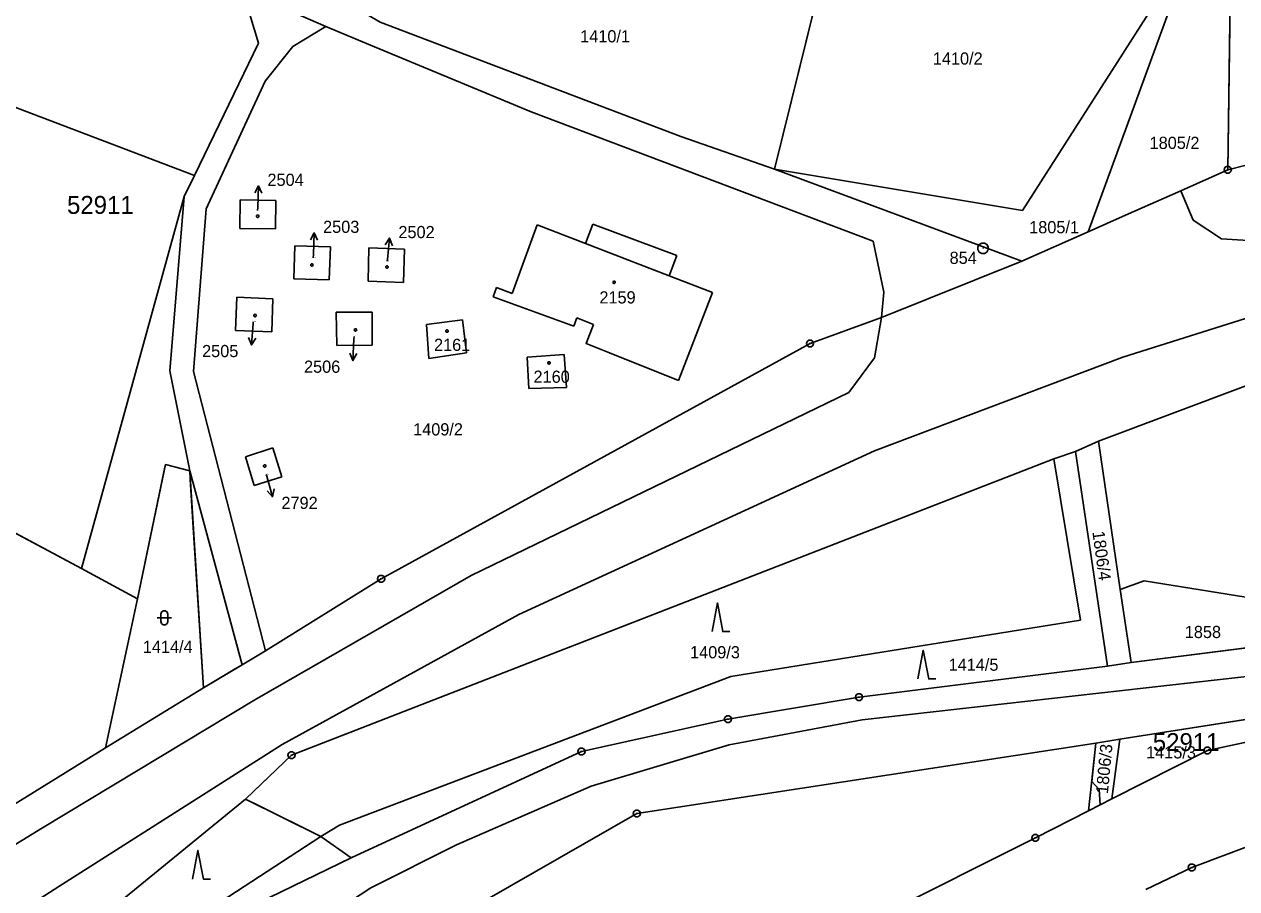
# Model space of a CAD drawing. Extents: x -779618 to -776429, y -1144546 to -1143350.
# Drawn here: x -778303.8 to -778134.6, y -1143722.3 to -1143601.8 of the extents above; entities that cross this region are included whole.
import ezdxf

# ---------------------------------------------------------------- set-up
doc = ezdxf.new("R2010")
doc.units = 0
for name, color, linetype in [('1', 7, 'Continuous'), ('11', 7, 'Continuous'), ('12', 7, 'Continuous'), ('2', 7, 'Continuous'), ('3', 7, 'Continuous'), ('4', 7, 'Continuous'), ('5', 7, 'Continuous'), ('6', 7, 'Continuous'), ('7', 7, 'Continuous'), ('8', 7, 'Continuous')]:
    doc.layers.add(name, color=color, linetype=linetype)

msp = doc.modelspace()

# ---------------------------------------------------------------- linework, layer by layer
at = {"layer": '1'}
for p, q in [((-778199.09, -1143621.98), (-778188.17, -1143577.7)), ((-778164.47, -1143627.74), (-778140.52, -1143590.24)), ((-778155.33, -1143630.71), (-778140.52, -1143590.24)), ((-778135.85, -1143622.07), (-778135.46, -1143593.27)), ((-778271.09, -1143604.41), (-778273.31, -1143597.02)), ((-778273.31, -1143597.02), (-778261.68, -1143602.09)), ((-778261.68, -1143602.09), (-778255.47, -1143604.68)), ((-778254.1, -1143601.46), (-778212.15, -1143617.44)), ((-778280.01, -1143622.84), (-778271.09, -1143604.41)), ((-778255.47, -1143604.68), (-778233.02, -1143613.98)), ((-778305.7, -1143613.08), (-778280.01, -1143622.84)), ((-778233.02, -1143613.98), (-778185.33, -1143632)), ((-778135.85, -1143622.07), (-778102.74, -1143613.61)), ((-778212.15, -1143617.44), (-778199.09, -1143621.98)), ((-778399.27, -1143622.42), (-778295.76, -1143677.67)), ((-778281.44, -1143625.81), (-778280.01, -1143622.84)), ((-778199.09, -1143621.98), (-778164.47, -1143627.74)), ((-778164.6, -1143634.82), (-778199.09, -1143621.98)), ((-778135.85, -1143622.07), (-778142.39, -1143624.98)), ((-778295.76, -1143677.67), (-778281.44, -1143625.81)), ((-778273.67, -1143630.26), (-778273.62, -1143626.25)), ((-778273.62, -1143626.25), (-778268.64, -1143626.37)), ((-778268.64, -1143626.37), (-778268.71, -1143630.32)), ((-778150.11, -1143628.4), (-778142.39, -1143624.98)), ((-778235.69, -1143639.3), (-778232.18, -1143629.74)), ((-778232.18, -1143629.74), (-778225.48, -1143632.35)), ((-778225.48, -1143632.35), (-778224.44, -1143629.63)), ((-778224.44, -1143629.63), (-778212.7, -1143634)), ((-778150.11, -1143628.4), (-778155.33, -1143630.71)), ((-778268.71, -1143630.32), (-778273.67, -1143630.26)), ((-778155.33, -1143630.71), (-778164.6, -1143634.82)), ((-778266.15, -1143637.28), (-778266.02, -1143632.68)), ((-778266.02, -1143632.68), (-778261.04, -1143632.82)), ((-778261.04, -1143632.82), (-778261.23, -1143637.42)), ((-778255.76, -1143637.61), (-778255.69, -1143632.97)), ((-778255.69, -1143632.97), (-778250.69, -1143633.13)), ((-778250.69, -1143633.13), (-778250.86, -1143637.79)), ((-778185.33, -1143632), (-778183.84, -1143639.14)), ((-778212.7, -1143634), (-778213.8, -1143636.84)), ((-778164.6, -1143634.82), (-778184.18, -1143642.68)), ((-778261.23, -1143637.42), (-778266.15, -1143637.28)), ((-778250.86, -1143637.79), (-778255.76, -1143637.61)), ((-778213.8, -1143636.84), (-778207.75, -1143639.17)), ((-778274.29, -1143644.46), (-778274.12, -1143639.83)), ((-778274.12, -1143639.83), (-778269.1, -1143640.05)), ((-778238.35, -1143639.77), (-778237.86, -1143638.48)), ((-778227.1, -1143643.89), (-778238.35, -1143639.77)), ((-778237.86, -1143638.48), (-778235.69, -1143639.3)), ((-778207.75, -1143639.17), (-778211.37, -1143648.55)), ((-778184.18, -1143642.68), (-778183.84, -1143639.14)), ((-778269.1, -1143640.05), (-778269.23, -1143644.64)), ((-778260.24, -1143641.93), (-778255.24, -1143641.93)), ((-778260.16, -1143646.56), (-778260.24, -1143641.93)), ((-778255.24, -1143641.93), (-778255.2, -1143646.51)), ((-778247.64, -1143643.63), (-778242.6, -1143643.01)), ((-778242.6, -1143643.01), (-778242.04, -1143647.59)), ((-778226.66, -1143642.73), (-778227.1, -1143643.89)), ((-778224.33, -1143643.62), (-778226.66, -1143642.73)), ((-778194.13, -1143646.31), (-778184.18, -1143642.68)), ((-778269.23, -1143644.64), (-778274.29, -1143644.46)), ((-778247.31, -1143648.36), (-778247.64, -1143643.63)), ((-778255.2, -1143646.51), (-778260.16, -1143646.56)), ((-778253.97, -1143679.1), (-778194.13, -1143646.31)), ((-778242.04, -1143647.59), (-778247.31, -1143648.36)), ((-778228.42, -1143647.83), (-778233.6, -1143648.2)), ((-778233.6, -1143648.2), (-778233.38, -1143652.56)), ((-778228.09, -1143652.44), (-778228.42, -1143647.83)), ((-778212.48, -1143651.43), (-778222.12, -1143647.61)), ((-778211.37, -1143648.55), (-778212.48, -1143651.43)), ((-778233.38, -1143652.56), (-778228.09, -1143652.44)), ((-778153.87, -1143659.9), (-778133.34, -1143652.18)), ((-778157.08, -1143661.33), (-778153.87, -1143659.9)), ((-778153.87, -1143659.9), (-778150.86, -1143680.58)), ((-778272.91, -1143662.07), (-778269.08, -1143660.84)), ((-778269.08, -1143660.84), (-778267.84, -1143664.89)), ((-778160.14, -1143662.37), (-778157.08, -1143661.33)), ((-778157.08, -1143661.33), (-778152.63, -1143691.27)), ((-778287.96, -1143681.89), (-778284.07, -1143663.17)), ((-778284.07, -1143663.17), (-778280.67, -1143664.05)), ((-778271.7, -1143666.07), (-778272.91, -1143662.07)), ((-778160.14, -1143662.37), (-778266.47, -1143703.7)), ((-778160.14, -1143662.37), (-778156.42, -1143684.85)), ((-778278.76, -1143694.3), (-778280.67, -1143664.05)), ((-778267.84, -1143664.89), (-778271.7, -1143666.07)), ((-778295.76, -1143677.67), (-778287.96, -1143681.89)), ((-778270.08, -1143689.13), (-778253.97, -1143679.1)), ((-778147.52, -1143679.38), (-778150.86, -1143680.58)), ((-778149.31, -1143690.75), (-778150.86, -1143680.58)), ((-778149.31, -1143690.75), (-778058.53, -1143679.28)), ((-778118.06, -1143684.08), (-778147.52, -1143679.38)), ((-778292.44, -1143702.68), (-778287.96, -1143681.89)), ((-778156.42, -1143684.85), (-778205.17, -1143692.74)), ((-778273.37, -1143691.09), (-778270.08, -1143689.13)), ((-778152.63, -1143691.27), (-778149.31, -1143690.75)), ((-778278.76, -1143694.3), (-778273.37, -1143691.09)), ((-778187.29, -1143695.6), (-778152.63, -1143691.27)), ((-778205.17, -1143692.74), (-778259.76, -1143713.44)), ((-778292.44, -1143702.68), (-778278.76, -1143694.3)), ((-778205.58, -1143698.68), (-778187.29, -1143695.6)), ((-778150.93, -1143701.48), (-778109.8, -1143695.04)), ((-778109.45, -1143696.76), (-778138.69, -1143703.04)), ((-778226.02, -1143703.2), (-778205.58, -1143698.68)), ((-778154.26, -1143702.04), (-778218.29, -1143711.84)), ((-778155.29, -1143711.47), (-778154.26, -1143702.04)), ((-778150.93, -1143701.48), (-778154.26, -1143702.04)), ((-778150.93, -1143701.48), (-778152.04, -1143709.77)), ((-778314.85, -1143716.56), (-778292.44, -1143702.68)), ((-778272.9, -1143709.81), (-778266.47, -1143703.7)), ((-778258.15, -1143717.99), (-778226.02, -1143703.2)), ((-778138.69, -1143703.04), (-778152.04, -1143709.77)), ((-778113.43, -1143708.98), (-778140.87, -1143719.35)), ((-778298.38, -1143730.62), (-778272.9, -1143709.81)), ((-778272.9, -1143709.81), (-778262.39, -1143715.02)), ((-778152.04, -1143709.77), (-778155.29, -1143711.47)), ((-778218.29, -1143711.84), (-778252.34, -1143731.3)), ((-778162.69, -1143715.23), (-778155.29, -1143711.47)), ((-778259.76, -1143713.44), (-778262.39, -1143715.02)), ((-778285.72, -1143730.23), (-778262.39, -1143715.02)), ((-778258.15, -1143717.99), (-778262.39, -1143715.02)), ((-778187.65, -1143727.69), (-778162.69, -1143715.23)), ((-778272.82, -1143725.14), (-778258.15, -1143717.99)), ((-778140.87, -1143719.35), (-778147.27, -1143722.43))]:
    msp.add_line(p, q, dxfattribs=at)
msp.add_lwpolyline([(-778224.33, -1143643.62), (-778225.38, -1143646.31), (-778222.12, -1143647.61)], dxfattribs=at)
at = {"layer": '11'}
for points in [[(-778309.93, -1143572.65), (-778265.53, -1143597.61), (-778264.74, -1143595.22), (-778254.1, -1143601.46), (-778212.15, -1143617.44), (-778199.09, -1143621.98), (-778194.74, -1143604.33), (-778188.17, -1143577.7), (-778140.52, -1143590.24), (-778144.08, -1143595.81), (-778135.53, -1143598.75), (-778135.85, -1143622.07)], [(-778391.62, -1143606.39), (-778399.27, -1143622.42), (-778398.95, -1143622.59), (-778295.76, -1143677.67), (-778287.96, -1143681.89), (-778284.15, -1143663.54), (-778284.07, -1143663.17), (-778280.67, -1143664.05), (-778280.59, -1143665.26), (-778280.22, -1143671.2), (-778278.76, -1143694.3)], [(-777931.96, -1143618.26), (-778063.42, -1143629.9), (-778133.34, -1143652.18), (-778153.87, -1143659.9), (-778157.08, -1143661.33), (-778160.14, -1143662.37), (-778266.47, -1143703.7), (-778271.68, -1143708.65), (-778272.9, -1143709.81), (-778271.17, -1143710.67), (-778262.39, -1143715.02), (-778258.15, -1143717.99), (-778226.02, -1143703.2), (-778205.58, -1143698.68), (-778187.29, -1143695.6), (-778152.63, -1143691.27), (-778149.31, -1143690.75), (-778058.53, -1143679.28), (-778043.88, -1143677.97), (-777959.48, -1143668.5)], [(-778278.76, -1143694.3), (-778274.32, -1143691.66), (-778273.37, -1143691.09), (-778270.08, -1143689.13), (-778253.97, -1143679.1), (-778194.13, -1143646.31), (-778184.18, -1143642.68), (-778164.6, -1143634.82), (-778155.33, -1143630.71), (-778150.11, -1143628.4), (-778142.39, -1143624.98), (-778135.85, -1143622.07)]]:
    msp.add_lwpolyline(points, dxfattribs=at)
msp.add_lwpolyline([(-778138.69, -1143703.04), (-778109.45, -1143696.76), (-778109.8, -1143695.04), (-778150.93, -1143701.48), (-778154.26, -1143702.04), (-778154.84, -1143707.34), (-778153.79, -1143708.48), (-778153.66, -1143710.62), (-778152.04, -1143709.77)], close=True, dxfattribs=at)
at = {"layer": '12'}
for p, q in [((-778273.67, -1143630.26), (-778273.62, -1143626.25)), ((-778273.62, -1143626.25), (-778268.64, -1143626.37)), ((-778268.64, -1143626.37), (-778268.71, -1143630.32)), ((-778235.69, -1143639.3), (-778232.18, -1143629.74)), ((-778232.18, -1143629.74), (-778225.48, -1143632.35)), ((-778268.71, -1143630.32), (-778273.67, -1143630.26)), ((-778266.15, -1143637.28), (-778266.02, -1143632.68)), ((-778266.02, -1143632.68), (-778261.04, -1143632.82)), ((-778261.04, -1143632.82), (-778261.23, -1143637.42)), ((-778255.76, -1143637.61), (-778255.69, -1143632.97)), ((-778255.69, -1143632.97), (-778250.69, -1143633.13)), ((-778250.69, -1143633.13), (-778250.86, -1143637.79)), ((-778225.48, -1143632.35), (-778213.8, -1143636.84)), ((-778261.23, -1143637.42), (-778266.15, -1143637.28)), ((-778250.86, -1143637.79), (-778255.76, -1143637.61)), ((-778213.8, -1143636.84), (-778207.75, -1143639.17)), ((-778274.29, -1143644.46), (-778274.12, -1143639.83)), ((-778274.12, -1143639.83), (-778269.1, -1143640.05)), ((-778238.35, -1143639.77), (-778237.86, -1143638.48)), ((-778227.1, -1143643.89), (-778238.35, -1143639.77)), ((-778237.86, -1143638.48), (-778235.69, -1143639.3)), ((-778207.75, -1143639.17), (-778211.37, -1143648.55)), ((-778269.1, -1143640.05), (-778269.23, -1143644.64)), ((-778260.24, -1143641.93), (-778255.24, -1143641.93)), ((-778260.16, -1143646.56), (-778260.24, -1143641.93)), ((-778255.24, -1143641.93), (-778255.2, -1143646.51)), ((-778247.64, -1143643.63), (-778242.6, -1143643.01)), ((-778242.6, -1143643.01), (-778242.04, -1143647.59)), ((-778226.66, -1143642.73), (-778227.1, -1143643.89)), ((-778224.33, -1143643.62), (-778226.66, -1143642.73)), ((-778269.23, -1143644.64), (-778274.29, -1143644.46)), ((-778247.31, -1143648.36), (-778247.64, -1143643.63)), ((-778255.2, -1143646.51), (-778260.16, -1143646.56)), ((-778242.04, -1143647.59), (-778247.31, -1143648.36)), ((-778228.42, -1143647.83), (-778233.6, -1143648.2)), ((-778233.6, -1143648.2), (-778233.38, -1143652.56)), ((-778228.09, -1143652.44), (-778228.42, -1143647.83)), ((-778212.48, -1143651.43), (-778222.12, -1143647.61)), ((-778211.37, -1143648.55), (-778212.48, -1143651.43)), ((-778233.38, -1143652.56), (-778228.09, -1143652.44)), ((-778272.91, -1143662.07), (-778269.08, -1143660.84)), ((-778269.08, -1143660.84), (-778267.84, -1143664.89)), ((-778271.7, -1143666.07), (-778272.91, -1143662.07)), ((-778267.84, -1143664.89), (-778271.7, -1143666.07))]:
    msp.add_line(p, q, dxfattribs=at)
msp.add_lwpolyline([(-778224.33, -1143643.62), (-778225.38, -1143646.31), (-778222.12, -1143647.61)], dxfattribs=at)
at = {"layer": '3'}
msp.add_lwpolyline([(-778284.72, -1143684.03), (-778284.62, -1143683.74), (-778284.37, -1143683.56), (-778284.06, -1143683.56), (-778283.81, -1143683.74), (-778283.71, -1143684.03), (-778283.71, -1143685.03), (-778283.81, -1143685.32), (-778284.06, -1143685.5), (-778284.37, -1143685.5), (-778284.62, -1143685.32), (-778284.72, -1143685.03)], close=True, dxfattribs=at)
for points in [[(-778207.8, -1143686.45), (-778207.05, -1143682.45), (-778206.3, -1143686.45), (-778205.3, -1143686.45)], [(-778285.22, -1143684.53), (-778283.95, -1143684.53), (-778283.22, -1143684.53)], [(-778179.08, -1143693.06), (-778178.33, -1143689.06), (-778177.58, -1143693.06), (-778176.58, -1143693.06)], [(-778280.27, -1143720.98), (-778279.52, -1143716.98), (-778278.77, -1143720.98), (-778277.77, -1143720.98)]]:
    msp.add_lwpolyline(points, dxfattribs=at)
at = {"layer": '4'}
for p, q in [((-778261.68, -1143602.09), (-778266.28, -1143604.87)), ((-778266.28, -1143604.87), (-778270.13, -1143609.7)), ((-778278.4, -1143627.53), (-778270.13, -1143609.7)), ((-778283.47, -1143650.09), (-778281.44, -1143625.81)), ((-778140.68, -1143629.11), (-778142.39, -1143624.98)), ((-778280.17, -1143650.2), (-778278.4, -1143627.53)), ((-778140.68, -1143629.11), (-778136.75, -1143631.7)), ((-778225.48, -1143632.35), (-778213.8, -1143636.84)), ((-778136.75, -1143631.7), (-778130.6, -1143632.07)), ((-778117.12, -1143637.64), (-778150.48, -1143648.2)), ((-778185.12, -1143648.27), (-778184.18, -1143642.68)), ((-778185.12, -1143648.27), (-778188.71, -1143653.12)), ((-778185.13, -1143661.25), (-778150.48, -1143648.2)), ((-778283.47, -1143650.09), (-778280.67, -1143664.05)), ((-778270.08, -1143689.13), (-778280.17, -1143650.2)), ((-778188.71, -1143653.12), (-778241.42, -1143678.62)), ((-778185.13, -1143661.25), (-778234.77, -1143684.06)), ((-778273.37, -1143691.09), (-778280.67, -1143664.05)), ((-778271.61, -1143695.99), (-778241.42, -1143678.62)), ((-778267.79, -1143702.21), (-778234.77, -1143684.06)), ((-778301.23, -1143713.82), (-778271.61, -1143695.99)), ((-778298.93, -1143721.99), (-778267.79, -1143702.21)), ((-778301.23, -1143713.82), (-778336.67, -1143735.43)), ((-778331.87, -1143743.04), (-778298.93, -1143721.99))]:
    msp.add_line(p, q, dxfattribs=at)
at = {"layer": '5'}
for points in [[(-778271.2, -1143628.37), (-778271.1, -1143628.39), (-778271.05, -1143628.48), (-778271.03, -1143628.54), (-778271.05, -1143628.63), (-778271.13, -1143628.7), (-778271.2, -1143628.71), (-778271.29, -1143628.68), (-778271.35, -1143628.62), (-778271.37, -1143628.54), (-778271.35, -1143628.45), (-778271.27, -1143628.38)], [(-778263.63, -1143635.17), (-778263.53, -1143635.19), (-778263.48, -1143635.28), (-778263.46, -1143635.34), (-778263.48, -1143635.43), (-778263.56, -1143635.5), (-778263.63, -1143635.51), (-778263.72, -1143635.48), (-778263.78, -1143635.42), (-778263.8, -1143635.34), (-778263.78, -1143635.25), (-778263.7, -1143635.18)], [(-778253.16, -1143635.45), (-778253.06, -1143635.47), (-778253.01, -1143635.56), (-778252.99, -1143635.62), (-778253.01, -1143635.71), (-778253.09, -1143635.78), (-778253.16, -1143635.79), (-778253.25, -1143635.76), (-778253.31, -1143635.7), (-778253.33, -1143635.62), (-778253.31, -1143635.53), (-778253.23, -1143635.46)], [(-778221.47, -1143637.59), (-778221.37, -1143637.61), (-778221.32, -1143637.7), (-778221.3, -1143637.76), (-778221.32, -1143637.85), (-778221.4, -1143637.92), (-778221.47, -1143637.93), (-778221.56, -1143637.9), (-778221.62, -1143637.84), (-778221.64, -1143637.76), (-778221.62, -1143637.67), (-778221.54, -1143637.6)], [(-778271.56, -1143642.22), (-778271.46, -1143642.24), (-778271.41, -1143642.33), (-778271.39, -1143642.39), (-778271.41, -1143642.48), (-778271.49, -1143642.55), (-778271.56, -1143642.56), (-778271.65, -1143642.53), (-778271.71, -1143642.47), (-778271.73, -1143642.39), (-778271.71, -1143642.3), (-778271.63, -1143642.23)], [(-778257.55, -1143644.23), (-778257.45, -1143644.25), (-778257.4, -1143644.34), (-778257.38, -1143644.4), (-778257.4, -1143644.49), (-778257.48, -1143644.56), (-778257.55, -1143644.57), (-778257.64, -1143644.54), (-778257.7, -1143644.48), (-778257.72, -1143644.4), (-778257.7, -1143644.31), (-778257.62, -1143644.24)], [(-778244.79, -1143644.38), (-778244.69, -1143644.4), (-778244.64, -1143644.49), (-778244.62, -1143644.55), (-778244.64, -1143644.64), (-778244.72, -1143644.71), (-778244.79, -1143644.72), (-778244.88, -1143644.69), (-778244.94, -1143644.63), (-778244.96, -1143644.55), (-778244.94, -1143644.46), (-778244.86, -1143644.39)], [(-778230.55, -1143648.83), (-778230.45, -1143648.85), (-778230.4, -1143648.94), (-778230.38, -1143649), (-778230.4, -1143649.09), (-778230.48, -1143649.16), (-778230.55, -1143649.17), (-778230.64, -1143649.14), (-778230.7, -1143649.08), (-778230.72, -1143649), (-778230.7, -1143648.91), (-778230.62, -1143648.84)], [(-778270.21, -1143663.2), (-778270.11, -1143663.22), (-778270.06, -1143663.31), (-778270.04, -1143663.37), (-778270.06, -1143663.46), (-778270.14, -1143663.53), (-778270.21, -1143663.54), (-778270.3, -1143663.51), (-778270.36, -1143663.45), (-778270.38, -1143663.37), (-778270.36, -1143663.28), (-778270.28, -1143663.21)]]:
    msp.add_lwpolyline(points, close=True, dxfattribs=at)
at = {"layer": '6'}
for p, q in [((-778186.87, -1143698.78), (-778058.2, -1143684.29)), ((-778205.43, -1143702.27), (-778186.87, -1143698.78)), ((-778224.68, -1143708.01), (-778205.43, -1143702.27)), ((-778243.47, -1143716.18), (-778224.68, -1143708.01)), ((-778255.4, -1143722.2), (-778243.47, -1143716.18)), ((-778255.4, -1143722.2), (-778270.22, -1143731.82))]:
    msp.add_line(p, q, dxfattribs=at)
at = {"layer": '7'}
for p, q in [((-778271.07, -1143624.31), (-778271.18, -1143627.31)), ((-778271.2, -1143627.73), (-778271.18, -1143627.31)), ((-778263.31, -1143630.87), (-778263.41, -1143633.87)), ((-778252.8, -1143631.6), (-778253.1, -1143634.59)), ((-778263.43, -1143634.34), (-778263.41, -1143633.87)), ((-778253.12, -1143634.82), (-778253.1, -1143634.59)), ((-778271.8, -1143643.27), (-778271.82, -1143643.5)), ((-778272.04, -1143646.49), (-778271.82, -1143643.5)), ((-778257.91, -1143648.67), (-778257.77, -1143645.67)), ((-778257.75, -1143645.29), (-778257.77, -1143645.67)), ((-778269.99, -1143664.56), (-778269.93, -1143664.77)), ((-778269.12, -1143667.66), (-778269.93, -1143664.77))]:
    msp.add_line(p, q, dxfattribs=at)
for points in [[(-778271.6, -1143625.29), (-778271.07, -1143624.31), (-778270.6, -1143625.33)], [(-778263.84, -1143631.85), (-778263.31, -1143630.87), (-778262.84, -1143631.89)], [(-778253.4, -1143632.55), (-778252.8, -1143631.6), (-778252.4, -1143632.65)], [(-778271.47, -1143645.53), (-778272.04, -1143646.49), (-778272.47, -1143645.46)], [(-778257.37, -1143647.69), (-778257.91, -1143648.67), (-778258.36, -1143647.64)], [(-778268.91, -1143666.56), (-778269.12, -1143667.66), (-778269.87, -1143666.83)]]:
    msp.add_lwpolyline(points, dxfattribs=at)
at = {"layer": '8'}
for p, q in [((-778135.97, -1143622.07), (-778135.73, -1143622.07)), ((-778170.03, -1143633), (-778169.93, -1143633)), ((-778194.25, -1143646.31), (-778194.01, -1143646.31)), ((-778254.09, -1143679.1), (-778253.85, -1143679.1)), ((-778187.41, -1143695.6), (-778187.17, -1143695.6)), ((-778205.7, -1143698.68), (-778205.46, -1143698.68)), ((-778266.59, -1143703.7), (-778266.35, -1143703.7)), ((-778226.14, -1143703.2), (-778225.9, -1143703.2)), ((-778138.81, -1143703.04), (-778138.57, -1143703.04)), ((-778218.41, -1143711.84), (-778218.17, -1143711.84)), ((-778162.81, -1143715.23), (-778162.57, -1143715.23)), ((-778140.99, -1143719.35), (-778140.75, -1143719.35))]:
    msp.add_line(p, q, dxfattribs=at)
for points in [[(-778135.7, -1143621.59), (-778135.45, -1143621.77), (-778135.35, -1143622.06), (-778135.45, -1143622.35), (-778135.7, -1143622.53), (-778136.01, -1143622.53), (-778136.26, -1143622.35), (-778136.36, -1143622.06), (-778136.26, -1143621.77), (-778136.01, -1143621.59)], [(-778169.79, -1143632.28), (-778169.45, -1143632.47), (-778169.26, -1143632.81), (-778169.26, -1143633.2), (-778169.45, -1143633.54), (-778169.79, -1143633.73), (-778170.18, -1143633.73), (-778170.52, -1143633.54), (-778170.71, -1143633.2), (-778170.71, -1143632.81), (-778170.52, -1143632.47), (-778170.18, -1143632.28)], [(-778193.98, -1143645.83), (-778193.73, -1143646.01), (-778193.63, -1143646.3), (-778193.73, -1143646.59), (-778193.98, -1143646.77), (-778194.29, -1143646.77), (-778194.54, -1143646.59), (-778194.64, -1143646.3), (-778194.54, -1143646.01), (-778194.29, -1143645.83)], [(-778253.82, -1143678.62), (-778253.57, -1143678.8), (-778253.47, -1143679.09), (-778253.57, -1143679.38), (-778253.82, -1143679.56), (-778254.13, -1143679.56), (-778254.38, -1143679.38), (-778254.48, -1143679.09), (-778254.38, -1143678.8), (-778254.13, -1143678.62)], [(-778187.14, -1143695.12), (-778186.89, -1143695.3), (-778186.79, -1143695.59), (-778186.89, -1143695.88), (-778187.14, -1143696.06), (-778187.45, -1143696.06), (-778187.7, -1143695.88), (-778187.8, -1143695.59), (-778187.7, -1143695.3), (-778187.45, -1143695.12)], [(-778205.43, -1143698.2), (-778205.18, -1143698.38), (-778205.08, -1143698.67), (-778205.18, -1143698.96), (-778205.43, -1143699.14), (-778205.74, -1143699.14), (-778205.99, -1143698.96), (-778206.09, -1143698.67), (-778205.99, -1143698.38), (-778205.74, -1143698.2)], [(-778138.54, -1143702.56), (-778138.29, -1143702.74), (-778138.19, -1143703.03), (-778138.29, -1143703.32), (-778138.54, -1143703.5), (-778138.85, -1143703.5), (-778139.1, -1143703.32), (-778139.2, -1143703.03), (-778139.1, -1143702.74), (-778138.85, -1143702.56)], [(-778266.32, -1143703.22), (-778266.07, -1143703.4), (-778265.97, -1143703.69), (-778266.07, -1143703.98), (-778266.32, -1143704.16), (-778266.63, -1143704.16), (-778266.88, -1143703.98), (-778266.98, -1143703.69), (-778266.88, -1143703.4), (-778266.63, -1143703.22)], [(-778225.87, -1143702.72), (-778225.62, -1143702.9), (-778225.52, -1143703.19), (-778225.62, -1143703.48), (-778225.87, -1143703.66), (-778226.18, -1143703.66), (-778226.43, -1143703.48), (-778226.53, -1143703.19), (-778226.43, -1143702.9), (-778226.18, -1143702.72)], [(-778218.14, -1143711.36), (-778217.89, -1143711.54), (-778217.79, -1143711.83), (-778217.89, -1143712.12), (-778218.14, -1143712.3), (-778218.45, -1143712.3), (-778218.7, -1143712.12), (-778218.8, -1143711.83), (-778218.7, -1143711.54), (-778218.45, -1143711.36)], [(-778162.54, -1143714.75), (-778162.29, -1143714.93), (-778162.19, -1143715.22), (-778162.29, -1143715.51), (-778162.54, -1143715.69), (-778162.85, -1143715.69), (-778163.1, -1143715.51), (-778163.2, -1143715.22), (-778163.1, -1143714.93), (-778162.85, -1143714.75)], [(-778140.72, -1143718.87), (-778140.47, -1143719.05), (-778140.37, -1143719.34), (-778140.47, -1143719.63), (-778140.72, -1143719.81), (-778141.03, -1143719.81), (-778141.28, -1143719.63), (-778141.38, -1143719.34), (-778141.28, -1143719.05), (-778141.03, -1143718.87)]]:
    msp.add_lwpolyline(points, close=True, dxfattribs=at)

# ---------------------------------------------------------------- texts
at = {"layer": '11'}
for p in [(-778297.79, -1143628.21), (-778146.31, -1143703.12)]:
    msp.add_text('52911', height=2.5, dxfattribs=at).set_placement(p)
at = {"layer": '2'}
for s, height, p in [('1410/1', 1.7, (-778226.2, -1143604.3)), ('1410/2', 1.7, (-778177, -1143607.4)), ('1805/2', 1.7, (-778146.76, -1143619.16)), ('2504', 0.1, (-778271.19, -1143627.73)), ('1805/1', 1.7, (-778163.56, -1143630.92)), ('2503', 0.1, (-778263.42, -1143634.34)), ('2502', 0.1, (-778253.11, -1143634.82)), ('2159', 1.7, (-778223.52, -1143640.71)), ('2505', 0.1, (-778271.79, -1143643.27)), ('2506', 0.1, (-778257.74, -1143645.29)), ('2161', 1.7, (-778246.59, -1143647.32)), ('2160', 1.7, (-778232.71, -1143651.77)), ('1409/2', 1.7, (-778249.51, -1143659.11)), ('2792', 0.1, (-778269.98, -1143664.56)), ('1858', 1.7, (-778141.85, -1143687.36)), ('1414/4', 1.7, (-778287.22, -1143689.43)), ('1409/3', 1.7, (-778210.87, -1143690.19)), ('1414/5', 1.7, (-778174.8, -1143691.92)), ('1415/3', 1.7, (-778147.25, -1143704.15))]:
    msp.add_text(s, height=height, dxfattribs=at).set_placement(p)
for s, rotation, p in [('1806/4', 277.8272, (-778154.75, -1143672.54)), ('1806/3', 84.6259, (-778152.58, -1143709.14))]:
    msp.add_text(s, height=1.7, rotation=rotation, dxfattribs=at).set_placement(p)
at = {"layer": '7'}
for s, p in [('2504', (-778269.83, -1143624.31)), ('2503', (-778262.07, -1143630.87)), ('2502', (-778251.56, -1143631.6)), ('2505', (-778278.95, -1143648.19)), ('2506', (-778264.73, -1143650.37)), ('2792', (-778267.88, -1143669.36))]:
    msp.add_text(s, height=1.7, dxfattribs=at).set_placement(p)
at = {"layer": '8'}
msp.add_text('854', height=1.7, dxfattribs=at).set_placement((-778174.66, -1143635.19))

doc.saveas('drawing.dxf')
